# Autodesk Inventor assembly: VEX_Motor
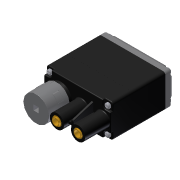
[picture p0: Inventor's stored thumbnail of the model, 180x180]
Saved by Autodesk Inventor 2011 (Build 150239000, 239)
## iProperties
Created: 2007-08
Part Number: VEX_Motor
Document SubType Name: Assembly
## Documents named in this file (9)
- C:\Data Folder\VEX 2011\Inventor Datasets\Unit 7\Components\VEX_Motor.iam
- C:\Data Folder\VEX 2011\Inventor Datasets\Unit 7\Components\Insert-Nut-632-Simple.ipt
- C:\Data Folder\VEX 2011\Inventor Datasets\Unit 7\Components\Vex-Motor-Top-Housing.ipt
- C:\Data Folder\VEX 2011\Inventor Datasets\Unit 7\Components\Vex-Motor-Output-Gear.ipt
- C:\Data Folder\VEX 2011\Inventor Datasets\Unit 7\Components\Vex-Motor-Bottom-Plate.ipt
- C:\Data Folder\VEX 2011\Inventor Datasets\Unit 7\Components\Vex-Motor-Bottom-Housing.ipt
- C:\Data Folder\VEX 2011\Inventor Datasets\Unit 7\Components\Vex-Wire-Support.ipt
- C:\Data Folder\VEX 2011\Inventor Datasets\Unit 7\Components\CLUTCH.iam
- C:\Data Folder\VEX 2011\Inventor Datasets\Unit 7\Components\Machine Screws.iam
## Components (9 placed, 8 different names)
1. Vex-Motor-Top-Housing — Insert:2, Mate:3, Mate:4, Mate:5, Mate:15, Mate:16, Insert:3
2. Vex-Motor-Bottom-Housing — Mate:3, Mate:4, Mate:5, Mate:6, Mate:7, Mate:8
3. Vex-Motor-Bottom-Plate — Mate:6, Mate:7, Mate:8, Mate:9, Mate:10, Mate:11
4. Insert-Nut-632-Simple — Mate:15
5. Insert-Nut-632-Simple — Mate:16
6. Vex-Motor-Output-Gear — Insert:1, Insert:2, Angle:1
7. Vex-Wire-Support — Mate:9, Mate:10, Mate:11
8. CLUTCH:1 [sub-assembly] — Insert:1, Angle:1
9. Machine Screws:1 [sub-assembly] — Insert:3
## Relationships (15: Mate 11, Insert 3, Angle 1)
- Insert:1: Vex-Motor-Output-Gear ↔ CLUTCH:1
- Insert:2: Vex-Motor-Top-Housing ↔ Vex-Motor-Output-Gear
- Mate:3: Vex-Motor-Top-Housing ↔ Vex-Motor-Bottom-Housing
- Mate:4: Vex-Motor-Top-Housing ↔ Vex-Motor-Bottom-Housing
- Mate:5: Vex-Motor-Top-Housing ↔ Vex-Motor-Bottom-Housing
- Mate:6: Vex-Motor-Bottom-Housing ↔ Vex-Motor-Bottom-Plate
- Mate:7: Vex-Motor-Bottom-Housing ↔ Vex-Motor-Bottom-Plate
- Mate:8: Vex-Motor-Bottom-Housing ↔ Vex-Motor-Bottom-Plate
- Mate:9: Vex-Motor-Bottom-Plate ↔ Vex-Wire-Support
- Mate:10: Vex-Motor-Bottom-Plate ↔ Vex-Wire-Support
- Mate:11: Vex-Motor-Bottom-Plate ↔ Vex-Wire-Support
- Angle:1: Vex-Motor-Output-Gear ↔ CLUTCH:1
- Mate:15: Vex-Motor-Top-Housing ↔ Insert-Nut-632-Simple
- Mate:16: Vex-Motor-Top-Housing ↔ Insert-Nut-632-Simple
- Insert:3: Vex-Motor-Top-Housing ↔ Machine Screws:1
